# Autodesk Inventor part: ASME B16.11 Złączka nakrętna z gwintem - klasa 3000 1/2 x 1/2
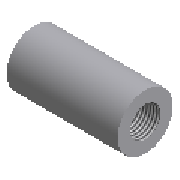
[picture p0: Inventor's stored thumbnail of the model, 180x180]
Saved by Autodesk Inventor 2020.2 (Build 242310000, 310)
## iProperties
Manager: www.cadconsulting.pl
Company: Fabian Stasiak CAD Consulting
NAME: PIPING: ASME B16.11 Coupling Threaded - Class 3000
DATA: <meta><inlinegroups number="1" deflen="6.0452"></inlinegroups><connections number="2"></connections><angles><a>3.14159265358979</a></angles></meta>
IsCustomPart: 0
Created: 2016-02
Part Number: ASME B16.11 Złączka nakrętna z gwintem - klasa 3000 1/2 x 1/2
Material: Stal
Description: Złączka nakrętna, gwintowana - klasa 3000
Document SubType Name: Modeling
Standard: ASME B16.11
Designer: F.Stasiak
Standard Revision: 2011
Standards Organization: ANSI
Language: pl-PL
Size Designation: 1/2 x 1/2
Categories: <MemberInstance><Categories><Category DisplayName="Rury cienko- i grubościenne" InternalName="4347fa0f-2144-441d-94cd-e3e15c92b736" Mnemonic="TUBEANDPIPE"><Cate
Density: 1 g/cm^3
Appearance: Płyta
Catalog Web Link: www.expertbooks.pl
Author: F.Stasiak
Subject: Zbiór ćwiczeń. Autodesk Inventor 2020. Kurs Professional
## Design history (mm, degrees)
sketch "Sketch1"
  geometry: L1 (0, 0)-(47.752, 0); L2 (47.752, 0)-(47.752, 9.16); L3 (47.752, 9.16)-(0, 9.16); L4 (0, 9.16)-(0, 0); L5 (47.752, 9.16)-(47.752, 14.224); L6 (47.752, 14.224)-(0, 14.224); L7 (0, 14.224)-(0, 9.16); L8 (0, 9.16)-(13.556, 8.737); L9 (23.876, 0)-(23.876, 14.224); L10 (47.752, 9.16)-(34.196, 8.737); L11 (13.556, 8.737)-(34.196, 8.737); L12 (13.556, 8.737)-(13.556, 0); L13 (34.196, 8.737)-(34.196, 0)
  constraints: 26 end point, 6 perpendicular, 2 midpoint, 2 parallel, 2 point on line, 1 horizontal, 1 symmetric about line, 1 other
  dimensions: "d0" = 18.32077 diameter of L3.end L1 (= MD); "d1" = 47.752 distance of L2.end L3.end (= W1); "d2" = 28.448 diameter of L6.end L1 (= D); "d3" = 1.78991 deg angle of L1 L8; "d4" = 13.55598 horizontal distance of L3.end L8.end (= L)
revolve "Revolve1" stored, may be unused: angle "d6" = 90 deg
workpoint "Work Point1"
workpoint "Work Point2"
workaxis "Work Axis1"
workpoint "Work Point3"
workaxis "Work Axis2"
workpoint "Work Point4"
body "Solid1"
feature "Gwint1" dims "d16" = 25.4, "d17" = 0
feature "Gwint2" dims "d18" = 25.4, "d19" = 0
other parameters: "W1" = 47.752 [user parameter; used in 1 equation term], "D" = 28.448 [user parameter; used in 1 equation term], "L" = 13.55598 [user parameter; used in 1 equation term], "MD" = 18.32077 [user parameter; used in 1 equation term], "Size_Designation" = 12.345 [user parameter]
